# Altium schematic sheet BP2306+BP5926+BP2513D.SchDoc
size A4
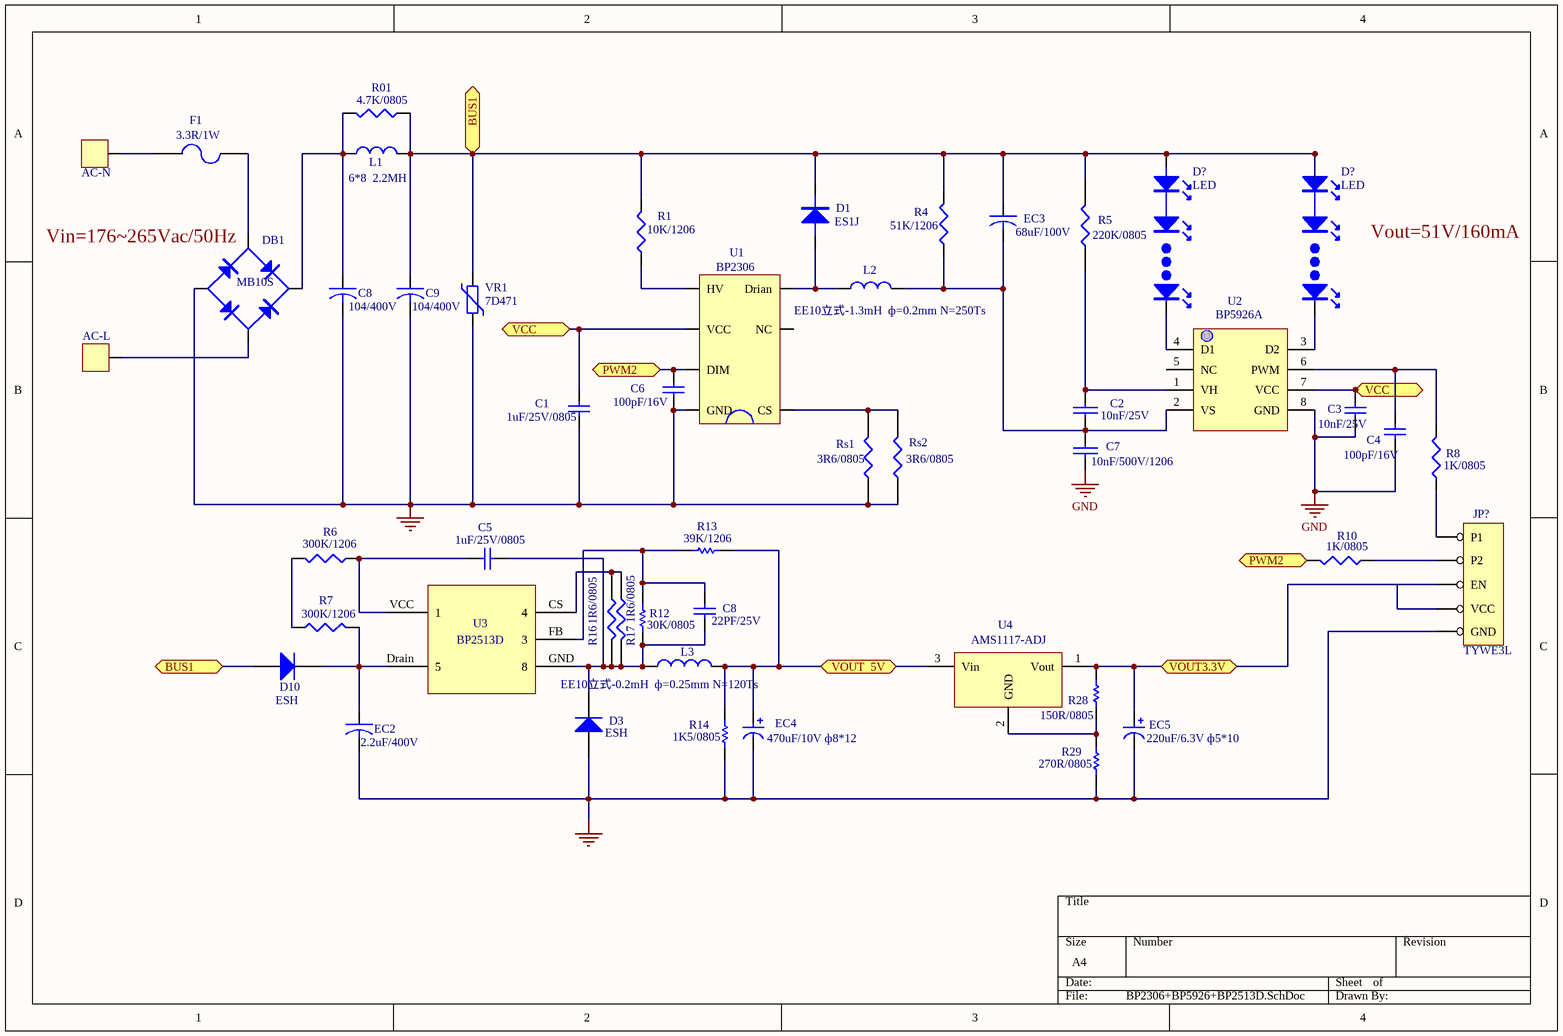
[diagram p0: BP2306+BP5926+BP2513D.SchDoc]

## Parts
(Parts that share a designator on the sheet are numbered #1, #2 ... from top to bottom, then left to right.)
AC-L  (no value)
AC-N  (no value)
C1  1uF/25V/0805  [C0805]
C2  10nF/25V  [0805B]
C3  10nF/25V  [C0805]
C4  100pF/16V  [C0805]
C5  value 1uF/25V/0805  [C0805]
C6  100pF/16V  [C0805]
C7  10nF/500V/1206  [0805B]
C8#1  104/400V
C8#2  value 22PF/25V  [C0805]
C9  104/400V
D1  ES1J  [SMA]
D3  ESH  [DO214]
D10  ESH  [DO214]
D?#1  LED
D?#2  LED
DB1  MB10S  [BRIDGE]
EC2  2.2uF/400V
EC3  68uF/100V  [R/S-0805(B)]
EC4  470uF/10V ф8*12  [CE0806]
EC5  220uF/6.3V ф5*10  [CE0806]
F1  3.3R/1W
JP?  TYWE3L
L1  6*8  2.2MH
L2  EE10立式-1.3mH  ф=0.2mm N=250Ts
L3  EE10立式-0.2mH  ф=0.25mm N=120Ts  [Toroid 9*4*4]
R01  4.7K/0805  [R/S-1206(B)]
R1  10K/1206  [R/S-1206(B)]
R4  51K/1206  [R/S-1206(B)]
R5  220K/0805  [0805B]
R6  300K/1206  [R/S-1206(B)]
R7  300K/1206  [R/S-1206(B)]
R8  1K/0805  [R/S-1206(B)]
R10  1K/0805  [R/S-1206(B)]
R12  30K/0805  [R0603]
R13  39K/1206  [R0603]
R14  1K5/0805  [R0603]
R16  1R6/0805  [0805B]
R17  1R6/0805  [0805B]
R28  150R/0805  [R0603]
R29  270R/0805  [R0603]
Rs1  3R6/0805  [0805B]
Rs2  3R6/0805  [0805B]
U1  BP2306
U2  BP5926A
U3  BP2513D  [SOT25]
U4  AMS1117-ADJ
VR1  7D471

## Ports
BUS1, PWM2, VCC, VOUT3.3V, VOUT  5V

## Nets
GND: C1.1 C3.1 C4.1 C6.1 C7.2 C8#1.2 C9.2 DB1.4(V-) Rs1.1 Rs2.1 U1.1(GND) U2.8(GND) VR1.1
GND1: D3.1(A) EC2.2 EC4.2 EC5.2 JP?.8(GND) R14.1 R29.1
BUS1: C9.1 D1.2(K) D10.1(A) D?#1.1 D?#2.1 EC3.1 L1.2 R01.1 R1.2 R4.2 R5.2 VR1.2 ; port BUS1
PWM2: C6.2 R10.2 U1.2(DIM) ; port PWM2
VCC: C1.2 C3.2 U1.3(VCC) U2.7(VCC) ; port VCC
VOUT3.3V: EC5.1 JP?.6(EN) JP?.7(VCC) R28.2 U4.1(Vout) ; port VOUT3.3V
VOUT  5V: EC4.1 L3.2 R13.1 R14.2 U4.3(Vin) ; port VOUT  5V
NetAC-L_?1: AC-L.?1 DB1.3(AC)
NetAC-N_?1: AC-N.?1 F1.1
NetC2_1: C2.1 R5.1 U2.1(VH)
NetC2_2: C2.2 C7.1 EC3.2 L2.2 R4.1 U2.2(VS)
NetC4_2: C4.2 R8.2 U2.6(PWM)
NetC5_1: C5.1 R6.1 U3.VCC(1)
NetC5_2: C5.2 C8#2.1 D3.2(K) L3.1 R12.1 R16.2 R17.2 U3.GND(8)
NetC8#1_1: C8#1.1 DB1.2(V+) L1.1 R01.2
NetC8#2_2: C8#2.2 R12.2 R13.2 U3.FB(3)
NetD1_1: D1.1(A) L2.1 U1.5(Drian)
NetD10_2: D10.2(K) EC2.1 R7.2 U3.Drain(5)
NetD?#1_2: D?#1.2 U2.4(D1)
NetD?#2_2: D?#2.2 U2.3(D2)
NetDB1_1: DB1.1(AC) F1.2
NetJP?_1: JP?.1(P1) R8.1
NetJP?_2: JP?.2(P2) R10.1
NetR1_1: R1.1 U1.4(HV)
NetR6_2: R6.2 R7.1
NetR16_1: R16.1 R17.1 U3.CS(4)
NetR28_1: R28.1 R29.2 U4.2(GND)
NetRs1_2: Rs1.2 Rs2.2 U1.7(CS)

Not connected (* = marked no-connect by the designer): U1 6(NC); U2 5(NC)

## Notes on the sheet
- Labels drawn without touching a wire or pin: Vin=176~265Vac/50Hz, Vout=51V/160mA

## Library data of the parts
AC-L AC-N = AC-L
C1 C3 C4 C6 = Cap: Capacitor; Value: 1uF/25V  0805
C2 C7 = CAP: Capacitor
C5 C8#2 = Cap: Capacitor
C8#1 C9 EC2 EC3 = CAPACITOR
D1 = DIODE
D3 D10 = SS23: Schottky Barrier Rectifier
DB1 = BRIDGE1: Diode Bridge
EC4 EC5 = 47uF/35V: Polarized Capacitor (Radial); Manufacturer: NICHICON; Manufacturer Part Number: UWT1V470MCL1GS
F1 = FUSE2: Fuse
JP? = 8 HEADER: 8 Pin Header
L1 L2 = INDUCTOR B
L3 = INDUCTOR: Code_IEC: 1005; Value: 2.5mH
R01 R1 R4 R6-R8 R10 = RES1A
R5 R16 R17 Rs1 Rs2 = RES1
R12-R14 R28 R29 = Res Semi: Semiconductor Resistor
U1 = BP287X
U2 = BP2839HJ
U3 = Component_1
U4 = 7805
VR1 = MOV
